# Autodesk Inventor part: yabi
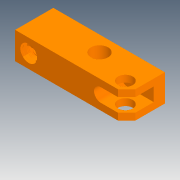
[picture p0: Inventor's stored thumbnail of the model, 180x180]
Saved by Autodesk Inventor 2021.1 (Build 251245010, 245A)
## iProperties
Created: 2021-05
Part Number: yabi
Material: Ogólny
Document SubType Name: Modeling
Designer: user
Density: 1 g/cm^3
Appearance: Domyślna
Author: user
Revision Number: ÈÎºÎ
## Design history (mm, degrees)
feature "Złożony1"
body "Srf1"
